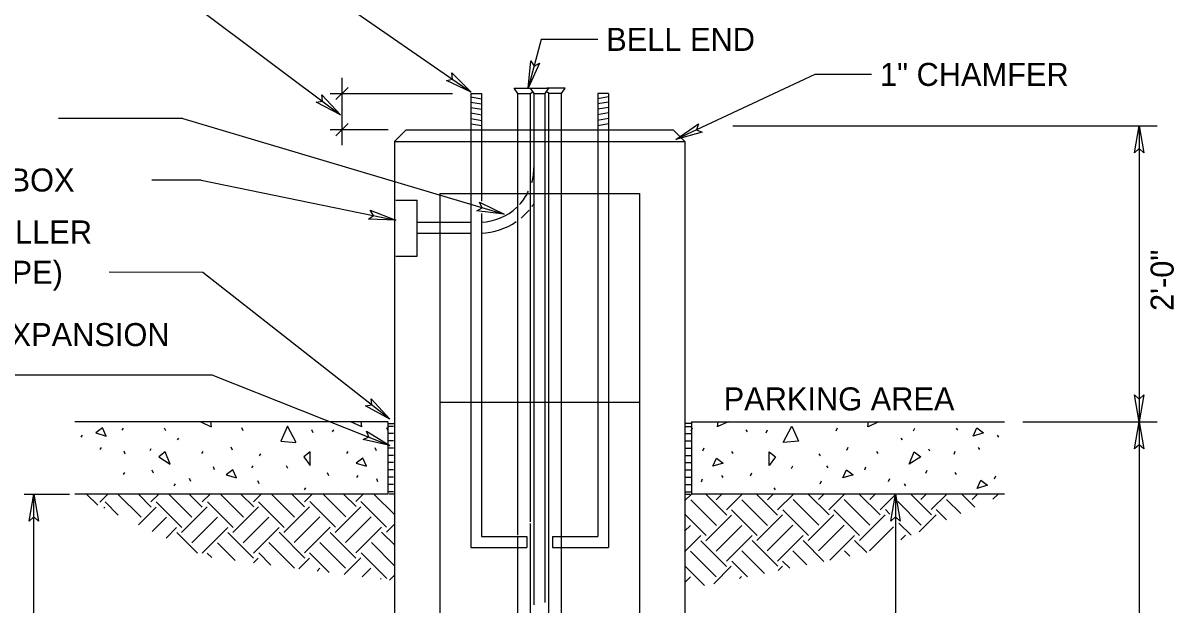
# Model space of a CAD drawing. Extents: x 99836 to 115004, y 99786 to 102182.
# Drawn here: x 105393 to 105993, y 101466 to 101769 of the extents above; entities that cross this region are included whole.
import ezdxf

# ---------------------------------------------------------------- set-up
doc = ezdxf.new("R2010")
doc.units = 0
doc.layers.add('Border Organizer Shape', color=7, linetype='Continuous')

msp = doc.modelspace()

# ---------------------------------------------------------------- linework, layer by layer
at = {"layer": 'Border Organizer Shape'}
for p, q in [((105478.83, 101835.56), (105626.51, 101733.48)), ((105482.86, 101778.16), (105558.35, 101721.62)), ((105662.97, 101760.97), (105656.25, 101735.57)), ((105692.43, 101760.95), (105662.97, 101760.97)), ((105559.07, 101705.84), (105559.07, 101741)), ((105805.76, 101742.72), (105733.2, 101708.77)), ((105835.23, 101742.7), (105805.76, 101742.72)), ((105555.87, 101729.54), (105562.26, 101735.92)), ((105648.93, 101735.57), (105658.39, 101735.57)), ((105650.82, 101732.73), (105648.93, 101735.57)), ((105657.44, 101735.57), (105666.9, 101735.57)), ((105659.33, 101732.73), (105657.44, 101735.57)), ((105665.01, 101732.73), (105666.9, 101735.57)), ((105675.42, 101735.57), (105665.96, 101735.57)), ((105673.52, 101732.73), (105675.42, 101735.57)), ((105552.92, 101732.73), (105616.76, 101732.73)), ((105626.22, 101732.73), (105626.22, 101713.81)), ((105626.22, 101732.73), (105631.9, 101732.73)), ((105626.22, 101730.98), (105631.91, 101730.04)), ((105631.9, 101732.73), (105631.9, 101713.81)), ((105650.82, 101732.73), (105657.44, 101732.73)), ((105650.82, 101713.81), (105650.82, 101732.73)), ((105657.44, 101732.73), (105658.39, 101733.68)), ((105657.44, 101713.81), (105657.44, 101732.73)), ((105659.33, 101732.73), (105665.01, 101732.73)), ((105659.33, 101713.81), (105659.33, 101732.73)), ((105665.01, 101713.81), (105665.01, 101732.73)), ((105666.9, 101732.73), (105665.96, 101733.68)), ((105673.52, 101732.73), (105666.9, 101732.73)), ((105666.9, 101713.81), (105666.9, 101732.73)), ((105673.52, 101713.81), (105673.52, 101732.73)), ((105698.12, 101730.98), (105692.43, 101730.04)), ((105692.44, 101732.73), (105692.44, 101713.81)), ((105698.12, 101732.73), (105692.44, 101732.73)), ((105698.12, 101732.73), (105698.12, 101713.81)), ((105626.22, 101728.26), (105631.91, 101727.32)), ((105626.22, 101725.45), (105631.91, 101724.51)), ((105698.12, 101728.26), (105692.43, 101727.32)), ((105698.12, 101725.45), (105692.43, 101724.51)), ((105476.1, 101719.74), (105411.22, 101719.8)), ((105476.1, 101719.74), (105643.61, 101669.86)), ((105555.87, 101710.72), (105562.26, 101717.11)), ((105626.3, 101722.65), (105631.98, 101721.71)), ((105626.3, 101719.69), (105631.98, 101718.75)), ((105626.3, 101716.96), (105631.98, 101716.02)), ((105698.04, 101722.65), (105692.36, 101721.71)), ((105698.04, 101719.69), (105692.36, 101718.75)), ((105698.12, 101716.91), (105692.44, 101715.98)), ((105552.92, 101713.91), (105583.16, 101713.91)), ((105592.52, 101713.81), (105586.49, 101707.78)), ((105592.52, 101713.81), (105731.83, 101713.81)), ((105626.22, 101713.81), (105626.22, 101496.23)), ((105631.9, 101713.81), (105631.9, 101676.59)), ((105650.82, 101502.52), (105650.82, 101713.81)), ((105657.44, 101509.63), (105657.44, 101713.81)), ((105659.33, 101466.36), (105659.33, 101713.81)), ((105665.01, 101467.43), (105665.01, 101713.81)), ((105666.9, 101397.25), (105666.9, 101713.81)), ((105673.52, 101397.25), (105673.52, 101713.81)), ((105692.44, 101713.81), (105692.44, 101501.91)), ((105698.12, 101713.81), (105698.12, 101496.23)), ((105731.83, 101713.81), (105737.85, 101707.78)), ((105762.9, 101715.92), (105984.32, 101715.92)), ((105974.86, 101715.92), (105974.86, 101561.62)), ((105586.49, 101707.78), (105586.49, 101186.18)), ((105586.49, 101707.78), (105737.85, 101707.78)), ((105737.85, 101707.78), (105737.85, 101186.18)), ((105485.6, 101687.66), (105459.95, 101687.67)), ((105485.6, 101687.66), (105587.17, 101666.83)), ((105587.17, 101677.16), (105598.32, 101677.16)), ((105598.32, 101647.91), (105598.32, 101677.16)), ((105610.14, 101680.7), (105610.14, 101209.83)), ((105610.14, 101680.7), (105714.2, 101680.7)), ((105714.2, 101680.7), (105714.2, 101209.83)), ((105631.9, 101670.18), (105631.9, 101501.91)), ((105598.32, 101665.72), (105626.05, 101665.72)), ((105598.32, 101660.04), (105626.05, 101660.04)), ((105587.17, 101647.91), (105598.32, 101647.91)), ((105486.47, 101639.55), (105437.7, 101639.58)), ((105583.94, 101563.12), (105486.47, 101639.55)), ((105370.79, 101586.12), (105491.25, 101586.12)), ((105491.25, 101586.12), (105584.04, 101549.41)), ((105610.14, 101571.91), (105714.2, 101571.91)), ((105582.92, 101561.62), (105419.64, 101561.62)), ((105583.03, 101561.62), (105583.05, 101524.03)), ((105583.25, 101560.79), (105586.12, 101560.79)), ((105741.1, 101560.79), (105738.22, 101560.79)), ((105741.31, 101561.62), (105741.29, 101524.03)), ((105741.43, 101561.62), (105904.71, 101561.62)), ((105914.17, 101561.62), (105984.32, 101561.62)), ((105974.86, 101561.62), (105974.86, 101325.24)), ((105444.87, 101558.28), (105444.19, 101557.27)), ((105467.11, 101556.9), (105466.43, 101558.41)), ((105507.45, 101556.95), (105506.78, 101558.45)), ((105544.03, 101556), (105543.34, 101557.51)), ((105554.66, 101557.48), (105553.99, 101556.47)), ((105583.13, 101556.95), (105582.46, 101558.45)), ((105585.91, 101559.31), (105583.03, 101559.31)), ((105585.91, 101555.53), (105583.03, 101555.53)), ((105738.44, 101559.31), (105741.31, 101559.31)), ((105738.44, 101555.53), (105741.31, 101555.53)), ((105741.21, 101556.95), (105741.88, 101558.45)), ((105769.68, 101557.48), (105770.36, 101556.47)), ((105780.32, 101556), (105781, 101557.51)), ((105816.89, 101556.95), (105817.56, 101558.45)), ((105857.24, 101556.9), (105857.92, 101558.41)), ((105879.48, 101558.28), (105880.15, 101557.27)), ((105423.54, 101554.72), (105422.87, 101553.71)), ((105473.82, 101553.22), (105473.15, 101552.21)), ((105585.91, 101551.74), (105583.03, 101551.74)), ((105738.44, 101551.74), (105741.31, 101551.74)), ((105850.52, 101553.22), (105851.19, 101552.21)), ((105900.8, 101554.72), (105901.47, 101553.71)), ((105433.5, 101548.33), (105432.82, 101547.32)), ((105446.04, 101544.85), (105445.37, 101546.36)), ((105459.43, 101547.62), (105458.76, 101546.61)), ((105486.45, 101546.19), (105485.78, 101545.18)), ((105502.01, 101546.89), (105501.34, 101548.4)), ((105516.57, 101545.03), (105515.9, 101544.01)), ((105562.13, 101546.19), (105561.46, 101545.18)), ((105576.98, 101546.53), (105576.31, 101548.04)), ((105585.91, 101547.96), (105583.03, 101547.96)), ((105585.91, 101544.17), (105583.03, 101544.17)), ((105738.44, 101547.96), (105741.31, 101547.96)), ((105738.44, 101544.17), (105741.31, 101544.17)), ((105747.36, 101546.53), (105748.03, 101548.04)), ((105762.21, 101546.19), (105762.88, 101545.18)), ((105807.77, 101545.03), (105808.44, 101544.01)), ((105822.33, 101546.89), (105823, 101548.4)), ((105837.89, 101546.19), (105838.56, 101545.18)), ((105864.91, 101547.62), (105865.58, 101546.61)), ((105878.3, 101544.85), (105878.98, 101546.36)), ((105890.85, 101548.33), (105891.52, 101547.32)), ((105492.63, 101536.66), (105491.96, 101538.18)), ((105512.51, 101538.76), (105511.84, 101537.75)), ((105530.82, 101537.29), (105530.15, 101538.8)), ((105585.91, 101540.39), (105583.03, 101540.39)), ((105738.44, 101540.39), (105741.31, 101540.39)), ((105793.52, 101537.29), (105794.19, 101538.8)), ((105811.83, 101538.76), (105812.5, 101537.75)), ((105831.71, 101536.66), (105832.38, 101538.18)), ((105445.58, 101535.19), (105444.9, 101534.18)), ((105460.73, 101534.98), (105460.06, 101536.49)), ((105480.25, 101530.57), (105479.57, 101532.08)), ((105515.92, 101529.31), (105515.25, 101530.83)), ((105552.22, 101533.51), (105551.55, 101535.03)), ((105567.29, 101533.72), (105566.62, 101532.71)), ((105577.83, 101530.36), (105577.15, 101531.88)), ((105585.91, 101536.61), (105583.03, 101536.61)), ((105585.91, 101532.82), (105583.03, 101532.82)), ((105738.44, 101536.61), (105741.31, 101536.61)), ((105738.44, 101532.82), (105741.31, 101532.82)), ((105746.52, 101530.36), (105747.19, 101531.88)), ((105757.06, 101533.72), (105757.73, 101532.71)), ((105772.12, 101533.51), (105772.8, 101535.03)), ((105808.42, 101529.31), (105809.09, 101530.83)), ((105844.1, 101530.57), (105844.77, 101532.08)), ((105863.61, 101534.98), (105864.28, 101536.49)), ((105878.77, 101535.19), (105879.44, 101534.18)), ((105899.49, 101532.04), (105900.17, 101533.55)), ((105472.02, 101529.31), (105471.34, 101528.3)), ((105540.01, 101527.21), (105539.33, 101526.2)), ((105585.91, 101529.04), (105583.03, 101529.04)), ((105585.91, 101525.25), (105583.03, 101525.25)), ((105738.44, 101529.04), (105741.31, 101529.04)), ((105738.44, 101525.25), (105741.31, 101525.25)), ((105784.34, 101527.21), (105785.01, 101526.2)), ((105852.33, 101529.31), (105853, 101528.3)), ((105393.2, 101524.03), (105416.87, 101524.03)), ((105398.29, 101446.84), (105398.29, 101524.03)), ((105583.05, 101524.03), (105419.64, 101524.03)), ((105425.88, 101524.03), (105431.68, 101518.23)), ((105432.75, 101519.85), (105436.93, 101524.03)), ((105435.52, 101519.94), (105442.39, 101513.07)), ((105442.13, 101524.03), (105454.25, 101511.92)), ((105452.84, 101524.03), (105459.6, 101517.27)), ((105459.41, 101519.94), (105463.5, 101524.03)), ((105462.08, 101519.94), (105475.46, 101506.56)), ((105468.69, 101524.03), (105480.81, 101511.91)), ((105479.4, 101524.03), (105486.17, 101517.26)), ((105486.17, 101519.94), (105490.26, 101524.03)), ((105488.94, 101520.04), (105502.32, 101506.66)), ((105495.65, 101524.03), (105507.67, 101512.01)), ((105506.35, 101524.03), (105513.02, 101517.36)), ((105512.83, 101520.03), (105516.83, 101524.03)), ((105515.5, 101520.03), (105528.88, 101506.65)), ((105522.21, 101524.03), (105534.23, 101512.01)), ((105532.91, 101524.03), (105539.59, 101517.36)), ((105539.59, 101520.03), (105543.59, 101524.03)), ((105542.36, 101520.13), (105555.74, 101506.75)), ((105549.16, 101524.03), (105561.09, 101512.11)), ((105559.86, 101524.03), (105566.44, 101517.46)), ((105566.25, 101520.13), (105570.16, 101524.03)), ((105568.92, 101520.13), (105582.3, 101506.75)), ((105575.72, 101524.03), (105586.59, 101513.17)), ((105586.61, 101523.88), (105583.74, 101523.88)), ((105586.33, 101524.13), (105586.61, 101523.84)), ((105737.73, 101523.88), (105740.6, 101523.88)), ((105737.74, 101520.48), (105741.29, 101524.03)), ((105741.01, 101521.08), (105754.39, 101507.71)), ((105904.71, 101524.03), (105741.29, 101524.03)), ((105748.77, 101524.03), (105759.74, 101513.06)), ((105754.2, 101521.08), (105757.15, 101524.03)), ((105759.55, 101515.73), (105767.86, 101524.03)), ((105767.58, 101521.08), (105780.96, 101507.7)), ((105775.33, 101524.03), (105786.31, 101513.05)), ((105780.96, 101521.08), (105783.91, 101524.03)), ((105786.31, 101515.73), (105794.61, 101524.03)), ((105794.43, 101521.18), (105807.81, 101507.8)), ((105802.28, 101524.03), (105813.16, 101513.15)), ((105807.62, 101521.17), (105810.48, 101524.03)), ((105812.97, 101515.82), (105821.18, 101524.03)), ((105821, 101521.17), (105834.38, 101507.79)), ((105828.84, 101524.03), (105839.73, 101513.15)), ((105834.38, 101521.17), (105837.24, 101524.03)), ((105839.73, 101515.82), (105847.94, 101524.03)), ((105847.76, 101524.03), (105847.76, 101331.05)), ((105849.04, 101520.09), (105861.23, 101507.89)), ((105855.79, 101524.03), (105866.58, 101513.25)), ((105861.04, 101521.27), (105863.81, 101524.03)), ((105866.39, 101515.92), (105874.51, 101524.03)), ((105874.42, 101521.27), (105881.79, 101513.9)), ((105882.35, 101524.03), (105889.21, 101517.18)), ((105887.8, 101521.27), (105890.56, 101524.03)), ((105898.54, 101521.31), (105901.27, 101524.03)), ((105434.8, 101516.73), (105435.33, 101517.26)), ((105452.86, 101508.03), (105462.08, 101517.26)), ((105475.37, 101503.98), (105488.75, 101517.36)), ((105502.13, 101503.98), (105515.5, 101517.36)), ((105528.79, 101504.07), (105542.17, 101517.45)), ((105555.55, 101504.07), (105568.92, 101517.45)), ((105737.75, 101513.64), (105749.04, 101502.35)), ((105748.85, 101499.67), (105762.23, 101513.05)), ((105762.23, 101515.73), (105775.61, 101502.35)), ((105775.51, 101499.77), (105788.89, 101513.15)), ((105789.08, 101515.83), (105802.46, 101502.45)), ((105802.27, 101499.77), (105815.65, 101513.15)), ((105815.65, 101515.82), (105829.03, 101502.44)), ((105828.93, 101499.86), (105842.31, 101513.24)), ((105842.5, 101515.92), (105844.84, 101513.58)), ((105860.17, 101504.34), (105869.07, 101513.24)), ((105869.07, 101515.92), (105874.37, 101510.62)), ((105460.08, 101504.56), (105467.44, 101511.91)), ((105480.72, 101498.63), (105494.1, 101512.01)), ((105507.48, 101498.63), (105520.86, 101512.01)), ((105534.14, 101498.72), (105547.52, 101512.1)), ((105539.49, 101493.37), (105552.87, 101506.75)), ((105560.9, 101498.72), (105574.28, 101512.1)), ((105566.25, 101493.37), (105579.63, 101506.75)), ((105582.21, 101504.17), (105586.57, 101508.53)), ((105657.44, 101397.25), (105657.44, 101508.65)), ((105737.78, 101504.66), (105740.82, 101507.7)), ((105754.2, 101494.32), (105767.58, 101507.7)), ((105780.86, 101494.42), (105794.24, 101507.79)), ((105807.62, 101494.42), (105821, 101507.79)), ((105834.28, 101494.51), (105846.79, 101507.02)), ((105849.57, 101508.85), (105855.88, 101502.54)), ((105467.3, 101501.08), (105472.79, 101506.56)), ((105472.89, 101503.98), (105483.68, 101493.19)), ((105486.07, 101493.28), (105499.45, 101506.65)), ((105499.45, 101503.98), (105512.83, 101490.6)), ((105512.83, 101493.28), (105526.21, 101506.65)), ((105526.31, 101504.08), (105539.68, 101490.7)), ((105552.87, 101504.07), (105566.25, 101490.69)), ((105579.73, 101504.17), (105586.54, 101497.36)), ((105631.9, 101501.91), (105655.55, 101501.91)), ((105650.82, 101397.25), (105650.82, 101501.64)), ((105655.55, 101501.91), (105655.55, 101496.23)), ((105668.79, 101501.91), (105692.44, 101501.91)), ((105668.79, 101501.91), (105668.79, 101496.23)), ((105737.8, 101493.98), (105746.17, 101502.35)), ((105759.55, 101488.97), (105772.93, 101502.35)), ((105786.21, 101489.06), (105799.59, 101502.44)), ((105813.47, 101489.56), (105826.35, 101502.44)), ((105850.57, 101500.09), (105853.01, 101502.54)), ((105494.1, 101498.63), (105503.36, 101489.36)), ((105520.95, 101498.73), (105534.26, 101485.43)), ((105547.52, 101498.72), (105560.9, 101485.34)), ((105574.38, 101498.82), (105586.51, 101486.68)), ((105626.22, 101496.23), (105655.55, 101496.23)), ((105668.79, 101496.23), (105698.12, 101496.23)), ((105746.17, 101499.67), (105759.55, 101486.3)), ((105773.03, 101499.77), (105786.41, 101486.39)), ((105799.59, 101499.77), (105810.42, 101488.94)), ((105826.45, 101499.87), (105832.82, 101493.49)), ((105483.68, 101493.19), (105483.69, 101493.19)), ((105488.75, 101493.28), (105491.1, 101490.93)), ((105512.87, 101488.15), (105515.41, 101490.69)), ((105515.6, 101493.38), (105521.99, 101486.99)), ((105536.6, 101485.13), (105542.17, 101490.69)), ((105542.17, 101493.37), (105552.43, 101483.11)), ((105560.17, 101482.12), (105568.83, 101490.79)), ((105569.02, 101493.47), (105582.4, 101480.09)), ((105740.82, 101494.32), (105754.2, 101480.94)), ((105762.33, 101489.07), (105770.55, 101480.85)), ((105767.68, 101494.42), (105779.44, 101482.65)), ((105788.89, 101489.06), (105792.62, 101485.33)), ((105794.24, 101494.42), (105801.52, 101487.14)), ((105821.1, 101494.52), (105823.92, 101491.69)), ((105546.09, 101483.92), (105547.52, 101485.34)), ((105569.66, 101480.91), (105574.18, 101485.44)), ((105737.82, 101486.62), (105748.14, 101476.3)), ((105753.03, 101477.29), (105762.13, 101486.39)), ((105786.61, 101484.11), (105788.89, 101486.39)), ((105579.15, 101479.7), (105579.53, 101480.09)), ((105583.9, 101479.1), (105586.5, 101481.7)), ((105737.84, 101477.96), (105740.82, 101480.94)), ((105766.46, 101480.02), (105767.48, 101481.04))]:
    msp.add_line(p, q, dxfattribs=at)
for points in [[(105662.17, 101748.59), (105656.25, 101735.57), (105657.54, 101749.81), (105659.29, 101747.06)], [(105616.27, 101743.47), (105626.51, 101733.48), (105613.55, 101739.53), (105616.73, 101740.24)], [(105548.5, 101731.99), (105558.35, 101721.62), (105545.63, 101728.16), (105548.83, 101728.75)], [(105746.98, 101712.58), (105733.2, 101708.77), (105744.96, 101716.91), (105743.96, 101713.81)], [(105972.47, 101701.82), (105974.86, 101715.92), (105977.26, 101701.82), (105974.86, 101704.03)], [(105630.77, 101676.17), (105643.61, 101669.86), (105629.41, 101671.59), (105632.22, 101673.25)], [(105573.84, 101672.01), (105587.17, 101666.83), (105572.88, 101667.32), (105575.53, 101669.22)], [(105574.32, 101573.71), (105583.94, 101563.12), (105571.36, 101569.94), (105574.58, 101570.46)], [(105977.25, 101575.72), (105974.86, 101561.62), (105972.47, 101575.72), (105974.86, 101573.51)], [(105977.25, 101575.72), (105974.86, 101561.62), (105972.47, 101575.72), (105974.86, 101573.51)], [(105972.47, 101547.52), (105974.86, 101561.62), (105977.26, 101547.52), (105974.86, 101549.73)], [(105571.81, 101556.82), (105584.04, 101549.41), (105570.05, 101552.37), (105572.99, 101553.78)], [(105395.9, 101509.93), (105398.29, 101524.03), (105400.69, 101509.93), (105398.29, 101512.15)], [(105845.36, 101509.93), (105847.76, 101524.03), (105850.15, 101509.93), (105847.76, 101512.15)]]:
    msp.add_lwpolyline(points, close=True, dxfattribs=at)
for points in [[(105485.51, 101561.62), (105490.85, 101559.14)], [(105491.01, 101559.08), (105490.65, 101561.62)], [(105563.86, 101561.62), (105569.19, 101559.15)], [(105569.35, 101559.09), (105568.99, 101561.62)], [(105754.99, 101559.09), (105755.35, 101561.62)], [(105760.48, 101561.62), (105755.15, 101559.15)], [(105833.33, 101559.08), (105833.69, 101561.62)], [(105838.84, 101561.62), (105833.49, 101559.14)], [(105436.11, 101554.27), (105434.09, 101558.47), (105430.73, 101555.95), (105436.11, 101554.27)], [(105535.23, 101550.83), (105530.7, 101559.41), (105527.17, 101551.51), (105535.07, 101550.83)], [(105789.11, 101550.83), (105793.65, 101559.41), (105797.17, 101551.51), (105789.28, 101550.83)], [(105888.24, 101554.27), (105890.25, 101558.47), (105893.61, 101555.95), (105888.24, 101554.27)], [(105469.52, 101539.52), (105466.79, 101546.02), (105463.44, 101543.5), (105469.52, 101539.52)], [(105542.46, 101538.89), (105542.47, 101546.02), (105539.12, 101543.5), (105542.46, 101538.89)], [(105781.88, 101538.89), (105781.87, 101546.02), (105785.23, 101543.5), (105781.88, 101538.89)], [(105854.82, 101539.52), (105857.55, 101546.02), (105860.91, 101543.5), (105854.82, 101539.52)], [(105571.88, 101538.52), (105569.86, 101542.72), (105566.5, 101540.2), (105571.88, 101538.52)], [(105752.47, 101538.52), (105754.48, 101542.72), (105757.84, 101540.2), (105752.47, 101538.52)], [(105504.1, 101532.43), (105502.08, 101536.63), (105498.72, 101534.12), (105504.1, 101532.43)], [(105820.25, 101532.43), (105822.26, 101536.63), (105825.62, 101534.12), (105820.25, 101532.43)], [(105890.34, 101526.98), (105892.35, 101531.18), (105895.71, 101528.66), (105890.34, 101526.98)]]:
    msp.add_lwpolyline(points, dxfattribs=at)
for radius, start, end in [(28.38, 344.30141, 0), (28.38, 317.39154, 334.44534), (34.06, 323.62856, 326.96454), (28.38, 271.91021, 313.44854), (34.06, 309.63547, 319.42298), (34.06, 271.59176, 304.32994)]:
    msp.add_arc((105630.78, 101694.1), radius, start, end, dxfattribs=at)

# ---------------------------------------------------------------- texts
for s, p in [(' BELL END', (105692.43, 101754.95)), (' 1" CHAMFER', (105835.23, 101736.7)), ('2" x 4" JUNCTION BOX ', (105249.44, 101681.67)), ('JOINT SEALING FILLER', (105249.44, 101654.58)), ('(HOT POURED TYPE) ', (105249.44, 101633.58)), ('1" PREFORMED EXPANSION ', (105249.44, 101601.12)), ('PARKING AREA', (105758.15, 101567.62))]:
    msp.add_text(s, height=12, dxfattribs=at).set_placement(p)
msp.add_text('2\'-0"', height=12, rotation=90, dxfattribs=at).set_placement((105992.86, 101619.41))

doc.saveas('drawing.dxf')
